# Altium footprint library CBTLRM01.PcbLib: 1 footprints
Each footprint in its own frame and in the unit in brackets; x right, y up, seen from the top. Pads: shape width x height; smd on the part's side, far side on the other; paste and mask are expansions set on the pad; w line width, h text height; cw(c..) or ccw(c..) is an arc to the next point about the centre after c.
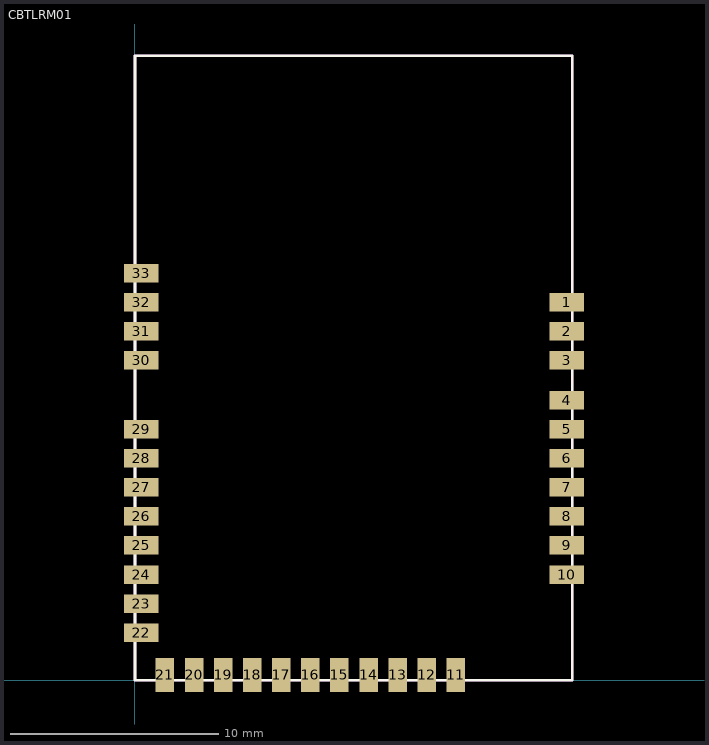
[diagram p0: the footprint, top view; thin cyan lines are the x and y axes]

## CBTLRM01 [mil]
pads (33):
  rect 65x35 smd mask+2.5: 1(816.77,715) 2(816.77,660) 3(816.77,605) 4(816.77,530) 5(816.77,475) 6(816.77,420) 7(816.77,365) 8(816.77,310) 9(816.77,255) 10(816.77,200) 22(11.77,90) 23(11.77,145) 24(11.77,200) 25(11.77,255) 26(11.77,310) 27(11.77,365) 28(11.77,420) 29(11.77,475) 30(11.77,605) 31(11.77,660) 32(11.77,715) 33(11.77,770)
  rect 35x65 smd mask+2.5: 11(606.77,10) 12(551.77,10) 13(496.77,10) 14(441.77,10) 15(386.77,10) 16(331.77,10) 17(276.77,10) 18(221.77,10) 19(166.77,10) 20(111.77,10) 21(56.77,10)
L26-Silk Screen Top (Multiple PADS layers...):
  lines w5: 0,0 0,1181.1 826.77,1181.1 826.77,0 0,0
L15 (Multiple PADS layers...):
  drawing of 37 lines, arcs and shapes, not listed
